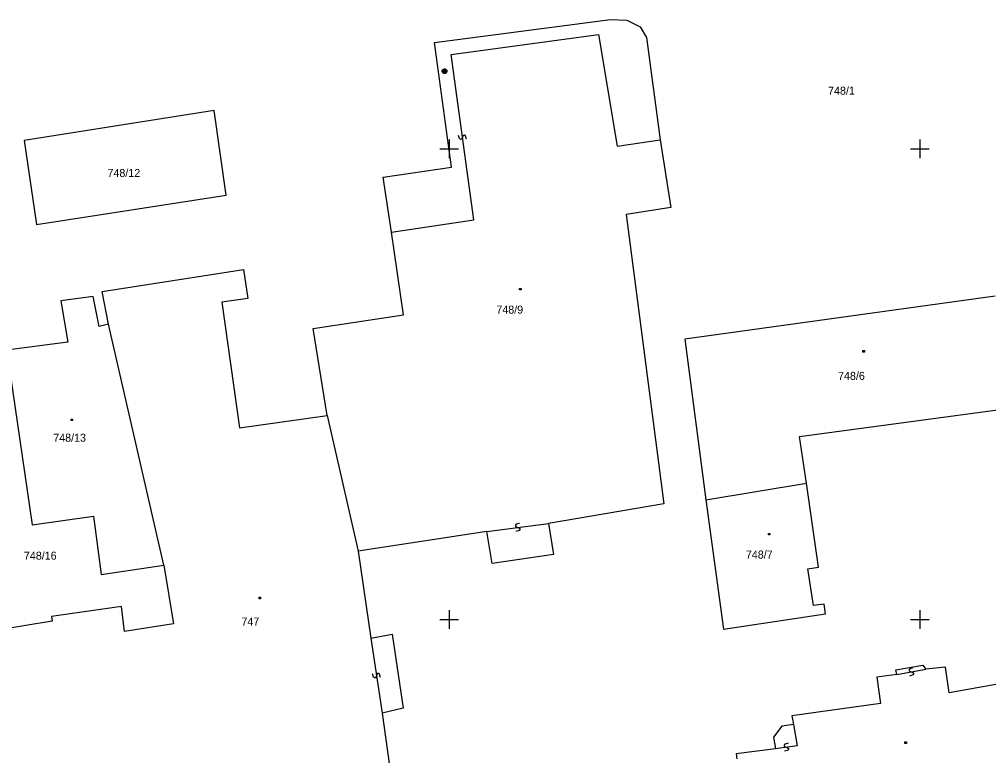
# Model space of a CAD drawing. Extents: x -493648 to -493033, y -1127718 to -1127026.
# Drawn here: x -493495.7 to -493392.7, y -1127614.5 to -1127536.2 of the extents above; entities that cross this region are included whole.
import ezdxf

# ---------------------------------------------------------------- set-up
doc = ezdxf.new("R2010")
doc.units = 0
doc.layers.add('katastrální mapa', color=7, linetype='Continuous')
doc.layers.add('síť', color=7, linetype='Continuous')

msp = doc.modelspace()

# ---------------------------------------------------------------- linework, layer by layer
at = {"layer": 'katastrální mapa'}
for p, q in [((-493451.55, -1127538.72), (-493432.87, -1127536.25)), ((-493432.87, -1127536.25), (-493431.12, -1127536.32)), ((-493431.12, -1127536.32), (-493429.7, -1127537.04)), ((-493429.7, -1127537.04), (-493429.04, -1127538.18)), ((-493449.76, -1127551.95), (-493451.55, -1127538.72)), ((-493449.79, -1127539.99), (-493434.12, -1127537.86)), ((-493434.12, -1127537.86), (-493432.15, -1127549.71)), ((-493429.04, -1127538.18), (-493427.57, -1127549.03)), ((-493447.36, -1127557.56), (-493449.79, -1127539.99)), ((-493450.73, -1127541.71), (-493450.68, -1127541.61)), ((-493450.73, -1127541.81), (-493450.73, -1127541.71)), ((-493450.68, -1127541.91), (-493450.73, -1127541.81)), ((-493450.68, -1127541.61), (-493450.63, -1127541.56)), ((-493450.63, -1127541.96), (-493450.68, -1127541.91)), ((-493450.63, -1127541.56), (-493450.53, -1127541.51)), ((-493450.63, -1127541.66), (-493450.63, -1127541.86)), ((-493450.63, -1127541.86), (-493450.53, -1127541.91)), ((-493450.53, -1127541.51), (-493450.43, -1127541.51)), ((-493450.53, -1127541.91), (-493450.53, -1127541.61)), ((-493450.53, -1127541.61), (-493450.43, -1127541.61)), ((-493450.43, -1127541.51), (-493450.33, -1127541.56)), ((-493450.43, -1127541.61), (-493450.43, -1127541.91)), ((-493450.43, -1127541.91), (-493450.33, -1127541.86)), ((-493450.33, -1127541.56), (-493450.28, -1127541.61)), ((-493450.33, -1127541.86), (-493450.33, -1127541.66)), ((-493450.28, -1127541.91), (-493450.33, -1127541.96)), ((-493450.28, -1127541.61), (-493450.23, -1127541.71)), ((-493450.23, -1127541.81), (-493450.28, -1127541.91)), ((-493450.23, -1127541.71), (-493450.23, -1127541.81)), ((-493450.53, -1127542.01), (-493450.63, -1127541.96)), ((-493450.43, -1127542.01), (-493450.53, -1127542.01)), ((-493450.33, -1127541.96), (-493450.43, -1127542.01)), ((-493474.94, -1127545.92), (-493495.13, -1127549.12)), ((-493473.7, -1127554.93), (-493474.94, -1127545.92)), ((-493495.13, -1127549.12), (-493493.83, -1127558.04)), ((-493448.91, -1127548.92), (-493449.01, -1127548.58)), ((-493448.8, -1127549.01), (-493448.91, -1127548.92)), ((-493448.7, -1127548.99), (-493448.8, -1127549.01)), ((-493448.61, -1127548.88), (-493448.7, -1127548.99)), ((-493448.54, -1127548.67), (-493448.61, -1127548.88)), ((-493448.45, -1127548.56), (-493448.54, -1127548.67)), ((-493448.35, -1127548.54), (-493448.45, -1127548.56)), ((-493448.24, -1127548.63), (-493448.35, -1127548.54)), ((-493448.14, -1127548.97), (-493448.24, -1127548.63)), ((-493432.15, -1127549.71), (-493427.57, -1127549.03)), ((-493427.57, -1127549.03), (-493426.45, -1127556.24)), ((-493457, -1127553.03), (-493449.76, -1127551.95)), ((-493456.11, -1127558.84), (-493457, -1127553.03)), ((-493493.83, -1127558.04), (-493473.7, -1127554.93)), ((-493426.45, -1127556.24), (-493431.18, -1127556.97)), ((-493431.18, -1127556.97), (-493430.08, -1127565.39)), ((-493456.11, -1127558.84), (-493447.36, -1127557.56)), ((-493454.84, -1127567.64), (-493456.11, -1127558.84)), ((-493486.86, -1127565.16), (-493471.84, -1127562.82)), ((-493471.84, -1127562.82), (-493471.38, -1127565.92)), ((-493486.17, -1127568.62), (-493486.86, -1127565.16)), ((-493442.51, -1127564.83), (-493442.36, -1127564.83)), ((-493442.51, -1127564.98), (-493442.51, -1127564.83)), ((-493442.36, -1127564.98), (-493442.51, -1127564.98)), ((-493442.36, -1127564.83), (-493442.36, -1127564.98)), ((-493430.08, -1127565.39), (-493427.2, -1127587.73)), ((-493487.82, -1127565.68), (-493491.26, -1127566.15)), ((-493491.26, -1127566.15), (-493490.49, -1127570.56)), ((-493487.18, -1127568.88), (-493487.82, -1127565.68)), ((-493471.38, -1127565.92), (-493474.13, -1127566.3)), ((-493474.13, -1127566.3), (-493472.25, -1127579.65)), ((-493391.99, -1127565.64), (-493424.97, -1127570.24)), ((-493464.43, -1127569.09), (-493454.84, -1127567.64)), ((-493486.17, -1127568.62), (-493487.18, -1127568.88)), ((-493480.3, -1127594.25), (-493486.17, -1127568.62)), ((-493462.97, -1127578.35), (-493464.43, -1127569.09)), ((-493490.49, -1127570.56), (-493497.03, -1127571.4)), ((-493424.97, -1127570.24), (-493422.74, -1127587.28)), ((-493406.03, -1127571.44), (-493405.88, -1127571.44)), ((-493406.03, -1127571.59), (-493406.03, -1127571.44)), ((-493405.88, -1127571.59), (-493406.03, -1127571.59)), ((-493405.88, -1127571.44), (-493405.88, -1127571.59)), ((-493496.66, -1127573.65), (-493494.3, -1127589.96)), ((-493412.77, -1127580.55), (-493390.67, -1127577.58)), ((-493490.16, -1127578.73), (-493490.01, -1127578.73)), ((-493490.16, -1127578.88), (-493490.16, -1127578.73)), ((-493490.01, -1127578.88), (-493490.16, -1127578.88)), ((-493490.01, -1127578.73), (-493490.01, -1127578.88)), ((-493472.25, -1127579.65), (-493462.97, -1127578.35)), ((-493462.97, -1127578.35), (-493459.65, -1127592.75)), ((-493412.03, -1127585.52), (-493412.77, -1127580.55)), ((-493422.74, -1127587.28), (-493412.03, -1127585.52)), ((-493410.74, -1127594.44), (-493412.03, -1127585.52)), ((-493427.2, -1127587.73), (-493439.45, -1127589.79)), ((-493422.74, -1127587.28), (-493420.86, -1127601.03)), ((-493494.3, -1127589.96), (-493487.78, -1127589.03)), ((-493487.78, -1127589.03), (-493486.95, -1127595.24)), ((-493445.98, -1127590.66), (-493439.45, -1127589.79)), ((-493442.86, -1127589.89), (-493442.95, -1127590)), ((-493442.95, -1127590), (-493442.93, -1127590.1)), ((-493442.93, -1127590.1), (-493442.82, -1127590.19)), ((-493442.52, -1127589.8), (-493442.86, -1127589.89)), ((-493442.82, -1127590.19), (-493442.61, -1127590.26)), ((-493442.61, -1127590.26), (-493442.5, -1127590.35)), ((-493439.45, -1127589.79), (-493438.91, -1127593.11)), ((-493445.98, -1127590.66), (-493459.65, -1127592.75)), ((-493445.43, -1127594.07), (-493445.98, -1127590.66)), ((-493442.57, -1127590.56), (-493442.91, -1127590.65)), ((-493442.48, -1127590.45), (-493442.57, -1127590.56)), ((-493442.5, -1127590.35), (-493442.48, -1127590.45)), ((-493416.06, -1127590.86), (-493415.91, -1127590.86)), ((-493416.06, -1127591.01), (-493416.06, -1127590.86)), ((-493415.91, -1127591.01), (-493416.06, -1127591.01)), ((-493415.91, -1127590.86), (-493415.91, -1127591.01)), ((-493459.65, -1127592.75), (-493458.3, -1127601.99)), ((-493438.91, -1127593.11), (-493445.43, -1127594.07)), ((-493486.95, -1127595.24), (-493480.3, -1127594.25)), ((-493480.3, -1127594.25), (-493479.27, -1127600.48)), ((-493411.88, -1127594.61), (-493410.74, -1127594.44)), ((-493411.3, -1127598.52), (-493411.88, -1127594.61)), ((-493470.19, -1127597.65), (-493470.04, -1127597.65)), ((-493470.19, -1127597.8), (-493470.19, -1127597.65)), ((-493470.04, -1127597.8), (-493470.19, -1127597.8)), ((-493470.04, -1127597.65), (-493470.04, -1127597.8)), ((-493410.17, -1127598.36), (-493411.3, -1127598.52)), ((-493410.02, -1127599.4), (-493410.17, -1127598.36)), ((-493484.8, -1127598.61), (-493492.23, -1127599.69)), ((-493484.49, -1127601.28), (-493484.8, -1127598.61)), ((-493420.86, -1127601.03), (-493410.02, -1127599.4)), ((-493492.17, -1127600.19), (-493505.05, -1127602.28)), ((-493492.23, -1127599.69), (-493492.17, -1127600.19)), ((-493479.27, -1127600.48), (-493484.49, -1127601.28)), ((-493458.3, -1127601.99), (-493456.05, -1127601.55)), ((-493456.05, -1127601.55), (-493454.87, -1127609.43)), ((-493458.3, -1127601.99), (-493457.12, -1127609.97)), ((-493457.49, -1127605.75), (-493457.59, -1127605.76)), ((-493457.38, -1127605.83), (-493457.49, -1127605.75)), ((-493402.55, -1127605.34), (-493399.66, -1127604.87)), ((-493402.43, -1127605.84), (-493402.55, -1127605.34)), ((-493402.43, -1127605.84), (-493399.37, -1127605.3)), ((-493401.06, -1127605.24), (-493401.14, -1127605.36)), ((-493401.14, -1127605.36), (-493401.12, -1127605.46)), ((-493401.12, -1127605.46), (-493401.01, -1127605.54)), ((-493400.72, -1127605.13), (-493401.06, -1127605.24)), ((-493401.01, -1127605.54), (-493400.79, -1127605.6)), ((-493400.79, -1127605.6), (-493400.68, -1127605.68)), ((-493400.68, -1127605.68), (-493400.66, -1127605.78)), ((-493399.66, -1127604.87), (-493399.37, -1127605.3)), ((-493397.27, -1127605.07), (-493399.37, -1127605.3)), ((-493396.87, -1127607.78), (-493397.27, -1127605.07)), ((-493458.04, -1127606.13), (-493458.14, -1127605.79)), ((-493457.93, -1127606.21), (-493458.04, -1127606.13)), ((-493457.83, -1127606.2), (-493457.93, -1127606.21)), ((-493457.74, -1127606.09), (-493457.83, -1127606.2)), ((-493457.68, -1127605.87), (-493457.74, -1127606.09)), ((-493457.59, -1127605.76), (-493457.68, -1127605.87)), ((-493457.28, -1127606.17), (-493457.38, -1127605.83)), ((-493402.43, -1127605.84), (-493404.55, -1127606.12)), ((-493404.55, -1127606.12), (-493404.16, -1127608.92)), ((-493400.74, -1127605.9), (-493401.08, -1127606.01)), ((-493400.66, -1127605.78), (-493400.74, -1127605.9)), ((-493389.11, -1127606.42), (-493396.87, -1127607.78)), ((-493454.87, -1127609.43), (-493457.12, -1127609.97)), ((-493404.16, -1127608.92), (-493413.58, -1127610.24)), ((-493457.12, -1127609.97), (-493455.52, -1127621.22)), ((-493413.58, -1127610.24), (-493413.42, -1127611.17)), ((-493414.66, -1127611.34), (-493415.52, -1127612.51)), ((-493413.42, -1127611.17), (-493414.66, -1127611.34)), ((-493413.42, -1127611.17), (-493413.03, -1127613.43)), ((-493415.52, -1127612.51), (-493415.33, -1127613.73)), ((-493415.33, -1127613.73), (-493419.51, -1127614.29)), ((-493413.03, -1127613.43), (-493415.33, -1127613.73)), ((-493414.32, -1127613.25), (-493414.41, -1127613.36)), ((-493414.41, -1127613.36), (-493414.4, -1127613.46)), ((-493414.4, -1127613.46), (-493414.29, -1127613.54)), ((-493414.04, -1127613.91), (-493414.38, -1127614.01)), ((-493413.98, -1127613.15), (-493414.32, -1127613.25)), ((-493414.29, -1127613.54), (-493414.07, -1127613.62)), ((-493414.07, -1127613.62), (-493413.96, -1127613.7)), ((-493413.95, -1127613.8), (-493414.04, -1127613.91)), ((-493413.96, -1127613.7), (-493413.95, -1127613.8)), ((-493401.57, -1127613.02), (-493401.42, -1127613.02)), ((-493401.57, -1127613.17), (-493401.57, -1127613.02)), ((-493401.42, -1127613.17), (-493401.57, -1127613.17)), ((-493401.42, -1127613.02), (-493401.42, -1127613.17)), ((-493419.51, -1127614.29), (-493419.45, -1127614.81))]:
    msp.add_line(p, q, dxfattribs=at)
at = {"layer": 'síť'}
for p, q in [((-493450, -1127549), (-493450, -1127551)), ((-493400, -1127549), (-493400, -1127551)), ((-493451, -1127550), (-493449, -1127550)), ((-493401, -1127550), (-493399, -1127550)), ((-493450, -1127599), (-493450, -1127601)), ((-493400, -1127599), (-493400, -1127601)), ((-493451, -1127600), (-493449, -1127600)), ((-493401, -1127600), (-493399, -1127600))]:
    msp.add_line(p, q, dxfattribs=at)

# ---------------------------------------------------------------- texts
at = {"layer": 'katastrální mapa'}
for s, p in [('748/1', (-493409.74, -1127544.25)), ('748/12', (-493486.29, -1127552.99)), ('748/9', (-493444.98, -1127567.51)), ('748/6', (-493408.68, -1127574.55)), ('748/13', (-493492.05, -1127581.12)), ('748/16', (-493495.17, -1127593.65)), ('748/7', (-493418.47, -1127593.53)), ('747', (-493472.06, -1127600.65))]:
    msp.add_text(s, height=0.849996, dxfattribs=at).set_placement(p)

doc.saveas('drawing.dxf')
